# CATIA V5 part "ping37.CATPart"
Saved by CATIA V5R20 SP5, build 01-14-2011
Part number: ping37
Material "DS star": density 1000 kg/m3
Material "Nylon": density 1200 kg/m3, Young's modulus 4e+09 Pa, Poisson ratio 0.4, thermal expansion 8e-05 1/K
Bounding box of the stored display mesh (mm): x -25 to 25, y -27 to 25, z 0 to 110
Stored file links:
  E:\180122237\yingliaoping\ping37.CATPart
  C:\Program Files\Dassault Systemes\B20\intel_a\startup\materials\Catalog.CATMaterial
  C:\Program Files\Dassault Systemes\B20\intel_a\startup\materials\brushed_metal2.jpg
  C:\Program Files\Dassault Systemes\B20\intel_a\startup\materials\eroded_metal_2.jpg
  C:\Program Files\Dassault Systemes\B20\intel_a\startup\materials\alpin_fir.jpg
  C:\Program Files\Dassault Systemes\B20\intel_a\startup\materials\DS_star.jpg
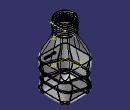
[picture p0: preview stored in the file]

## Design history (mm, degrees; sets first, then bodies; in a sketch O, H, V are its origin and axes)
Set1, material "无"
  Sketch1 on xy-plane, origin (0, 0, 0), H (1, 0, 0), V (0, 1, 0)
    line L1 (25, 25) -> (25, -25)
    line L2 (25, -25) -> (-25, -25)
    line L3 (-25, -25) -> (-25, 25)
    line L4 (-25, 25) -> (25, 25)
    length L1 = 50
    length L4 = 50
    vertical: L1 V, L3 V
    horizontal: L2 H, L4 H
    equidistance: L1 L3 O, L2 L4 O
  Sketch2 on face of Pad1 from Sketch1.L4, origin (0, 25, 0), H (-1, 0, 0), V (0, 0, 1)
    spline S1 through (-66.6318, 11.634) (-4.8013, 16.4925) (0, 14.9742) (43.9322, 22.262)
    point P1 (0, 14.9742)
    coincidence: P1 V
  Extrude1: Element1 Sketch2, Lim1 20, Lim2 72
  MultiSel1: CommonCtxFeats ({extract ExtractElem face of Fillet1}; {extract ExtractElem face of Pad1 from Sketch1.L3}; {extract ExtractElem face of Fillet1}; {extract ExtractElem face of Pad1 from Sketch1.L4}; {extract ExtractElem face of Fillet1}; {extract ExtractElem face of Pad1 from Sketch1.L1}; {extract ExtractElem face of Fillet1}; {extract ExtractElem face of Pad1 from Sketch1.L2})
  Sketch3 on face of Pad1 from Sketch1.L2, origin (0, -25, 0), H (1, 0, 0), V (0, 0, 1)
    spline S1 through (-42.7837, 39.2471) (-16.5466, 28.2612) (-2.9034, 31.9232) (39.863, 28.2612)
  Extrude2: Element1 Sketch3, Lim1 20, Lim2 72
  MultiSel2: CommonCtxFeats ({extract ExtractElem face of Pad1 from Sketch1.L2}; {extract ExtractElem face of Fillet1}; {extract ExtractElem face of Pad1 from Sketch1.L1}; {extract ExtractElem face of Fillet1}; {extract ExtractElem face of Pad1 from Sketch1.L4}; {extract ExtractElem face of Fillet1}; {extract ExtractElem face of Pad1 from Sketch1.L3}; {extract ExtractElem face of Fillet1})
  Join1: Elements ({intersect ToIntersect1 {extract ExtractElem face of Fillet1}, ToIntersect2 Extrude1}; {intersect ToIntersect1 {extract ExtractElem face of Pad1 from Sketch1.L3}, ToIntersect2 Extrude1}; {intersect ToIntersect1 {extract ExtractElem face of Fillet1}, ToIntersect2 Extrude1}; {intersect ToIntersect1 {extract ExtractElem face of Pad1 from Sketch1.L4}, ToIntersect2 Extrude1}; {intersect ToIntersect1 {extract ExtractElem face of Fillet1}, ToIntersect2 Extrude1}; {intersect ToIntersect1 {extract ExtractElem face of Pad1 from Sketch1.L1}, ToIntersect2 Extrude1}; {intersect ToIntersect1 {extract ExtractElem face of Fillet1}, ToIntersect2 Extrude1}; {intersect ToIntersect1 {extract ExtractElem face of Pad1 from Sketch1.L2}, ToIntersect2 Extrude1})
  Join2: Elements ({intersect ToIntersect1 {extract ExtractElem face of Pad1 from Sketch1.L2}, ToIntersect2 Extrude2}; {intersect ToIntersect1 {extract ExtractElem face of Fillet1}, ToIntersect2 Extrude2}; {intersect ToIntersect1 {extract ExtractElem face of Pad1 from Sketch1.L1}, ToIntersect2 Extrude2}; {intersect ToIntersect1 {extract ExtractElem face of Fillet1}, ToIntersect2 Extrude2}; {intersect ToIntersect1 {extract ExtractElem face of Pad1 from Sketch1.L4}, ToIntersect2 Extrude2}; {intersect ToIntersect1 {extract ExtractElem face of Fillet1}, ToIntersect2 Extrude2}; {intersect ToIntersect1 {extract ExtractElem face of Pad1 from Sketch1.L3}, ToIntersect2 Extrude2}; {intersect ToIntersect1 {extract ExtractElem face of Fillet1}, ToIntersect2 Extrude2})
  Plane1: type Normal, Curve Join2, RefPoint vertex [face of MultiSel2 | face of MultiSel2]
  Circle1: type CtrRad, Start 0, End 180, Center vertex [face of MultiSel2 | face of MultiSel2], Support Plane1, Radius 1, FirstDirection (1, 0, 0)
Body1 (main body), material "Nylon"
  Pad1: profile Sketch1, direction (0, 0, 1), length 50
  Fillet1: on edge [face of Pad1 from Sketch1.L4 | face of Pad1 from Sketch1.L1]; edge [face of Pad1 from Sketch1.L1 | face of Pad1 from Sketch1.L2]; edge [face of Pad1 from Sketch1.L2 | face of Pad1 from Sketch1.L3]; edge [face of Pad1 from Sketch1.L3 | face of Pad1 from Sketch1.L4]
  Plane2: type Offset, RefPlane end face of Pad1, Offset 40, reversed
  Sketch4 on Plane2, origin (0, 0, 90), H (1, 0, 0), V (0, -1, 0)
    circle A1 centre (0, 0) radius 15
    radius A1 = 15
  Pad2: profile Sketch4, direction (0, 0, 1), length 20
  Sketch5 on end face of Pad1, origin (0, 0, 50), H (1, 0, 0), V (0, 1, 0)
    point P1 (0, 25)
    distance P1 H = 25
    coincidence: P1 V
  Sketch6 on Plane2, origin (0, 0, 90), H (1, 0, 0), V (0, -1, 0)
    point P1 (0, -15)
    distance P1 H = 15
    coincidence: P1 V
  Slot1: profile Circle1, centre curve Join2
  Plane3: type Normal, Curve Join1, RefPoint vertex [face of MultiSel1 | face of MultiSel1]
  Circle2: type CtrRad, Start 0, End 180, Center vertex [face of MultiSel1 | face of MultiSel1], Support Plane3, Radius 1, FirstDirection (-1, 0, 0)
  Slot2: profile Circle2, centre curve Join1
  Fillet2: radius 8, on start face of Pad1
  Loft1: solid, Sections ({boundary Boundary {extract ExtractElem start face of Pad2}}; {boundary Boundary {extract ExtractElem end face of Pad1}}), StartFace start face of Pad2, EndFace end face of Pad1
  Shell1: ExtOffset 0, Face end face of Pad2, IntOffset 1
  Plane4: type Offset, RefPlane Plane2, Offset 2, reversed
  Sketch7 on Plane4, origin (0, 0, 92), H (1, 0, 0), V (0, -1, 0)
    point P1 (15, 0)
    distance P1 V = 15
    coincidence: P1 H
  Helix1: Direction Z axis, RefPoint Sketch7, Pitch 3, Height 16, TaperAngle 0
  Point1: type OnCurve, Support Helix1, RefPoint Sketch7, Length 5
  Line1: type PtDir, RefPoint Sketch7, Direction (1, 0, 0), Start 0, End 5
  Connect1: Curve1 Line1, Point1 vertex of Line1, Tension1 1, Curve2 Helix1, Point2 Point1, Tension2 1
  Point2: type OnCurve, Support Connect1, RefPoint vertex of Helix1, Length -5
  Line2: type PtDir, RefPoint vertex of Helix1, Direction (0, 1, 0), Start 0, End 10
  Connect2: Curve1 Line2, Point1 vertex of Line2, Tension1 1, Curve2 Connect1, Point2 Point2, Tension2 1
  Plane5: type Normal, Curve Connect2, RefPoint vertex of Connect2
  Circle3: type CtrRad, Start 0, End 180, Center vertex of Connect2, Support Plane5, Radius 1, FirstDirection (-1, 0, 0)
  Rib1: profile Circle3, centre curve Connect2
  Body2
    Sketch8 on end face of Pad2, origin (0, 0, 110), H (1, 0, 0), V (0, 1, 0)
      circle A1 centre (0, 0) radius 14
      radius A1 = 14
    Pad3: profile Sketch8, direction (0, 0, -1), length 20
  Remove1: tool Body2
  Loft2: solid, Sections ({boundary Boundary {extract ExtractElem start face of Pad2}}; {boundary Boundary {extract ExtractElem end face of Pad1}}), StartFace start face of Pad2, EndFace end face of Pad1
Body3, material "DS star"
  Sketch9 on face of Pad1 from Sketch1.L2, origin (0, -25, 0), H (1, 0, 0), V (0, 0, 1)
    polyline C1
    polyline C2
    polyline C3
    polyline C4
    polyline C5
    polyline C6
    polyline C7
    polyline C8
    polyline C9
    polyline C10
    polyline C11
    polyline C12
  Pad4: profile Sketch9, direction (0, -1, 0), length 2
